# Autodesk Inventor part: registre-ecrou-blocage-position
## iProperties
Author: chr
Created: 2001-06
Part Number: registre-ecrou-blocage-position
Material: Par défaut
Document SubType Name: Modélisation
Designer: chr
Control State: 0
Master: False
Checked Out: False
PropertySet Name: Design Tracking Control
Shininess: 20.0
PropertySet Name: _Private Model Information
Length Units: 11269
Angle Units: 11286
Time Units: 11279
Mass Units: 11290
Length Display Precision: 3
Angle Display Precision: 2
Compacted: False
Density: 0.0
Volumn: 0.0
Area: 0.0
PropertySet Name: Model Information
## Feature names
1. Extrusion1
2. Congé1 [Fillet]
3. Extrusion2
4. Extrusion3
